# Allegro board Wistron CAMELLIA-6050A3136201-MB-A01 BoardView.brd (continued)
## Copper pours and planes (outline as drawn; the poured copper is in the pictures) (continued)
VRP1V8A on BOTTOM: 117.49,92.31 116.89,91.72 117.05,91.56 114.7,89.22 114.43,89.22 111.89,91.76 111.78,91.76 111.25,92.29 111.25,93.89 114.2,96.84 115.47,96.84 118.64,93.66 118.64,93.16 117.68,92.19 117.64,92.17
VRP1V8A_PH on BOTTOM: 108.23,100.78 108.73,100.27 109.37,100.27 110,100.9 110.64,100.9 111.91,99.63 111.91,99.13 108.92,96.14 107.34,97.73 107.34,99.25 107.85,99.76 107.85,100.4
VRP1V8A_VIN on BOTTOM (solid shape): 105.58,102.53 105.58,102.12 106.27,101.44 106.58,101.44 107.29,100.73 107.29,100.67 106.7,100.09 104.87,100.09 104.62,100.34 104.19,100.34 104.02,100.18 103.74,100.18 102.1,101.82 102.1,102.99 101.11,103.98 101.11,105.22 101.88,105.98 102.13,105.98
VRP2V5 on BOTTOM: 201.42,7.43 201.42,3.24 202.94,3.24 202.94,4.26 203.07,4.38 205.23,4.38 205.36,4.51 205.36,7.3 205.23,7.43
VRP2V5_PH on BOTTOM: 200.53,7.3 200.53,3.37 200.4,3.24 197.1,3.24 196.97,3.37 196.97,4.64 197.1,4.76 198.5,4.76 198.62,4.89 198.62,7.3 198.75,7.43 200.4,7.43
VRP2V5_VIN on BOTTOM: 195.45,4.13 195.32,4 194.18,4 194.05,4.13 194.05,4.26 193.8,4.51 192.78,4.51 192.66,4.38 192.66,3.24 192.53,3.11 191.87,3.11 191.87,5.65 192.27,5.65 192.78,5.15 193.93,5.15 194.18,4.89 195.32,4.89 195.45,4.76
VRP3V3A on BOTTOM: 223.54,64.58 226.59,64.58 226.84,64.84 227.86,64.84 228.88,65.85 228.88,70.68 229.13,70.93 229.13,73.09 229,73.22 223.67,73.22 223.42,72.96 223.42,64.71
VRP3V3A_PH on BOTTOM (solid shape): 228.04,79.95 228.5,79.95 228.62,79.82 228.62,79.44 229.46,78.6 227.73,78.6 227.73,80.56 228.04,80.56
VRP3V3A_PH on BOTTOM: 227.73,78.81 228.62,78.81 228.62,78.68 230.53,78.68 230.78,78.42 230.78,76.27 230.53,76.01 225.19,76.01 224.94,76.27 224.94,78.04 225.32,78.42 227.48,78.42 227.73,78.68
VRP3V3A_VIN on BOTTOM: 225.57,81.85 225.96,81.47 226.84,81.47 226.97,81.35 226.97,80.46 227.23,80.2 227.48,80.2 227.48,80.58 227.86,80.96 227.86,87.11 227.78,87.19 226.08,87.19 225.57,86.68
VRP5V0 on BOTTOM: 240.43,63.06 240.94,63.57 241.83,63.57 241.96,63.69 241.96,65.72 240.69,66.99 237.39,66.99 237.26,66.87 237.26,66.36 236.24,65.34 235.73,65.34 235.1,65.98 233.45,65.98 233.32,65.85 233.32,65.34 232.31,64.33 232.31,63.06 233.19,63.06 233.45,63.31 233.45,63.57 233.58,63.69 235.23,63.69 235.86,63.06
VRP5V0_PH on BOTTOM (solid shape): 237.92,72.76 238.45,72.23 238.45,72.2 236.85,72.2 237.49,72.84 237.49,76.44 237.92,76.44
VRP5V0_PH on BOTTOM: 237.51,72.61 237.51,72.96 236.75,72.2 235.86,72.2 235.73,72.07 235.73,70.55 235.86,70.42 241.45,70.42 242.47,71.44 242.47,71.57 242.34,71.69 240.81,71.69 240.56,71.95 240.56,72.58 238.02,72.58 237.99,72.61
VRP5V0_VIN on BOTTOM: 235.35,76.65 235.1,76.39 233.7,76.39 233.58,76.27 233.58,73.6 233.7,73.47 236.62,73.47 237.26,74.11 237.26,76.65 237.77,77.15 237.77,79.95 237.64,80.08 237,80.08 236.12,79.19 235.86,79.19 235.86,78.04 235.35,77.54
VRP5V0A on BOTTOM: 186.2,91.12 193.06,91.12 193.7,90.49 193.7,86.68 184.68,86.68 184.55,86.81 184.55,88.33 186.08,89.85 186.08,91
VRP5V0A_PH on BOTTOM (solid shape): 189.96,97.14 189.96,96.36 190.4,95.92 190.4,93.92 190.27,93.79 185.82,93.79 185.7,93.92 185.7,95.52 186.1,95.92 186.1,96.64 186.15,96.69 187.33,96.69 187.48,96.84 189.05,96.84 189.43,97.22 189.89,97.22
VRP5V0A_VIN on BOTTOM (solid shape): 184.68,100.78 188.03,100.78 188.03,100.14 188.19,99.98 188.64,99.98 188.73,99.89 188.73,99.61 188.87,99.22 189.22,98.99 189.25,98.99 189.25,97.75 189.23,97.73 188.36,97.73 188.03,98.06 185.49,98.06 184.55,99 183.16,99 183.03,99.13 183.03,100.65 183.31,100.93 183.41,100.99 183.41,101.03 183.66,101.28 184.17,101.28
VRPCHG_HG1 on BOTTOM: 176.68,109.54 175.41,109.54 175.28,109.41 175.28,108.02 175.41,107.89 176.68,107.89 176.81,108.02 176.81,109.41
VRPCHG_HG2 on BOTTOM: 156.74,109.67 155.98,109.67 155.85,109.54 155.85,108.52 155.6,108.27 155.6,107.76 155.85,107.51 156.23,107.51 156.49,107.76 156.49,108.02 156.87,108.4 156.87,109.54
VRPCHG_LG1 on BOTTOM: 178.08,111.06 176.68,111.06 176.55,110.94 176.55,110.05 177.06,109.54 177.44,109.54 178.2,110.3 178.2,110.94
VRPCHG_LG2 on BOTTOM: 157.88,116.91 157.88,115.38 158.01,115.25 158.77,115.25 158.9,115.38 158.9,117.03 158.65,117.29 158.26,117.29
VRPCHG_PH1 on BOTTOM: 169.06,107.89 174.9,107.89 175.03,108.02 175.03,109.54 175.28,109.79 175.79,109.79 176.3,110.3 176.3,115.25 176.17,115.38 174.39,115.38 174.14,115.13 173.12,115.13 173,115.25 173,116.14 172.87,116.27 172.11,116.27 171.22,115.38 167.28,115.38 167.28,109.67
VRPCHG_PH2 on BOTTOM (solid shape): 163.22,110.81 162.33,109.92 155.9,109.92 155.9,113.43 155.22,114.11 155.22,114.75 155.47,115 163.22,115
VRPCPU_PH1 on BOTTOM: 143.12,103.62 145.59,103.62 145.64,103.57 145.64,100.27 145.89,100.01 148.94,100.01 148.94,97.22 141.75,97.22 141.63,97.35 141.63,100.27 141.75,100.4 142.9,100.4 143.02,100.52 143.02,103.52
VRPCPU_PH2 on BOTTOM: 116.81,101.17 118.56,102.92 118.62,102.92 120.96,100.59 121.32,100.59 122.23,101.5 124.23,99.51 124.23,99.38 120.8,95.95 120.55,95.95 118.01,98.49 118.01,99.8 116.81,100.99
VRPCPU_PH3 on BOTTOM: 127.48,100.83 129.22,102.57 129.29,102.57 131.63,100.24 131.98,100.24 134.14,102.39 134.9,101.64 134.9,97.47 134.77,97.35 130.77,97.35 127.48,100.65
VRPGT_PH1 on BOTTOM: 109.98,60.31 110.11,60.44 110.11,63.95 109.9,64.15 105.97,64.15 105.69,64.43 105.69,67.25 105.56,67.38 103.2,67.38 103.12,67.3 103.12,64.45 103.78,63.79 103.78,60.52 103.98,60.31
VRPRIM_VIN on BOTTOM (solid shape): 178.18,101.44 178.18,97.6 177.9,97.32 177.9,97.12 177.52,97.12 177.44,97.19 177.44,97.98 176.02,99.4 176.02,101.64 176.17,101.79 177.82,101.79
VRPSA_PH1 on BOTTOM: 151.41,102.05 153.18,102.05 153.18,100.27 153.06,100.14 153.06,98.62 153.31,98.36 154.84,98.36 155.09,98.62 156.36,98.62 156.49,98.49 156.49,95.7 151.66,95.7 151.28,96.08 151.28,101.92
VRPVCC_PRIM on BOTTOM: 173.38,88.33 173.38,87.95 173.5,87.82 173.89,87.82 174.52,87.19 180.87,87.19 181.25,87.57 181.25,90.36 180.49,91.12 176.04,91.12 175.66,91.51 175.66,92.52 175.54,92.65 174.01,92.65 173.89,92.52 173.89,88.84
VRPVCC_PRIM_PH on BOTTOM: 176.17,94.55 177.14,94.55 178.05,95.47 180.57,95.47 180.74,95.29 180.74,94.81 180.87,94.68 182.01,94.68 182.14,94.55 182.14,92.9 182.01,92.78 176.55,92.78 176.17,93.16
VRPVCCIO on BOTTOM: 112.44,55.46 112.44,50.74 112.7,50.48 115.85,50.48 115.97,50.61 115.97,51.12 115.59,51.5 115.59,52.26 116,52.67 116.13,52.67 116.23,52.77 116.23,53.15 116.86,53.79 118.13,53.79 118.26,53.91 118.26,54.65 118.16,54.75 116,54.75 115.77,54.98 115.77,55.26 115.57,55.46
VRPVCCIO_PH on BOTTOM: 105.56,54.12 105.46,54.22 104.44,54.22 104.44,54.57 105.81,54.57 106.68,55.44 107.72,55.44 107.85,55.56 107.85,56.71 107.97,56.83 109.24,56.83 109.39,56.68 109.39,51.5 106.32,51.5 106.32,51.88 105.56,52.64
VRPVCCIO_VIN on BOTTOM (solid shape): 103.4,54.07 104.19,54.07 104.19,53.66 103.02,53.66 102.71,53.35 102.71,52.98 101.87,52.14 98.88,52.14 98.4,52.62 98.4,53.08 98.5,53.18 98.54,53.2 98.8,53.2 98.93,53.33 98.93,54.17 103.3,54.17
VRPVDDQ on BOTTOM: 171.14,5.6 174.34,5.6 174.34,3.24 169.87,3.24 169.59,2.96 169.59,2.48 168.96,1.84 167.92,1.84 167.66,2.1 167.66,6.42 168.04,6.8 168.04,8.7 168.93,8.7 168.93,7.3 169.95,6.29 170.46,6.29
VRPVDDQ_PH on BOTTOM: 158.9,6.92 158.9,6.16 159.03,6.03 160.17,6.03 160.55,5.65 160.55,5.15 161.19,4.51 161.19,2.61 161.57,2.22 163.98,2.22 164.11,2.35 164.11,7.43 160.3,7.43 159.92,7.05 159.03,7.05
VRPVDDQ_VIN on BOTTOM (solid shape): 155.47,6.03 155.85,6.03 155.98,6.16 157.5,6.16 158.01,5.65 158.01,5.53 157.76,5.27 156.49,5.27 156.11,4.89 156.11,4.64 155.09,3.62 151.79,3.62 151.53,3.88 151.53,5.78 151.91,6.16 155.34,6.16
VRPVTT on TOP (solid shape): 160.04,10.35 160.04,9.34 160.68,8.7 160.68,7.94 160.42,7.69 159.92,7.69 159.66,7.94 159.66,8.57 159.41,8.83 158.39,8.83 158.14,8.57 158.14,8.32 158.01,8.19 157.76,8.19 157.63,8.32 157.63,8.83 158.14,9.34 158.14,10.86 158.52,11.24 159.15,11.24

Small or netless copper shapes (teardrops, artwork), in the pictures only: 2352 on TOP, 3084 on BOTTOM, 1684 on L3, 30 on L4, 822 on L5, 1427 on L6

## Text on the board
Ref Des/Silkscreen Bottom: 6050A3140501 | -ALS-A01(A1) | 6050A3136301-USB-A01(A1) | 6050A3194001-ALS-A01(A1) | HSN-I36C | HSN-I36C-4 | UMA
Ref Des/Silkscreen Top: CN9354 | MIC9352 | MIC9350 | CAMELLIA-6050A3136201-MB-A01(A1) | HSN-I36C | HSN-I36C-4 | UMA | 6050A3140701-MIC-A01(A1)
User.15: TP24_NP | 100pF_50V_1 | TOSHIBA_SSM3K15AMFV_3P | short_0201_10 | 1uF_6.3V_1 | 0.1uF_6.3V_1 | NXP_74LVC1G3157GM_TSOT886_6P | 2.2K_5%_1 | short_0402_15 | 10pF_50V_1 | 0.1uF_10V_1 | AMC_AZ5125_01H_SOD523_2P | FIX_MASK_0.8 | AMAZING_AZ1143_04F_R7G_10P | MCF08062G900_T | 4.7K_5%_1 | 1000pF_25V_1 | 68pF_50V_1 | 0_5%_1_NSP | 1uF_6.3V_2_NP | TI_SN74AUP1G97DCKR_SC70_6P_NP | TOSHIBA_SSM3K15AMFV_3P_NP | 0.022uF_6.3V_1 | 49.9_1%_1 | 6.8PF_50V_1 | 0.22uF_6.3V_2 | 100K_5%_1 | 0.022uF_16V_2 | short_0201_5 | 2200pF_16V_1 | 470K_1%_1 | NXP_74LVC1G17GM_TSOT886_6P | 0.22uF_6.3V_1 | NXP_PMBT3906YS_TSOT363_6P | NXP_NX5P3290AU_WLCSP_16P | 0.22uF_25V_1 | 0.33uF_25V_1 | short_0402_15_nsp | 1K_5%_1_NP | 10K_5%_1_NP | 100K_5%_1_NP | DIALOG_SLG4T43296VTR_STQFN_12P | 80.6_1%_1 | 200K_5%_1 | 6.04K_1%_1/16W_2 | 0.01UF_25V_1 | 220K_5%_1 | 2.2UF_6.3V_1 | 100K_1%_1 | NXP_74LVC1G08GW_TSOT353_5P | AMAZING_AZ5B75_01B_R7G_2P | 18pF_50V_1 | AMAZING_AZ5B8S_01F_R7G_2P | 220K_1%_1 | LITEON_LTW_C195DSKS_5A_4P | TP24 | 10uF_6.3V_2 | 4.7UF_6.3V_2 | 2.2UF_6.3V_2 | 33_5%_1 | 0.1uF_16V_2 | MST_MH255ESP_PSOT23_3P | Short_0805_50_NSP | 4.99K_1%_2 | KNOWLES_SPK0838HT4H_1_8P | CAPELLA_CM32181E_OPLGA_6P | 43.2K_1%_2 | 470pF_50V_2 | 150pF_50V_2 | short_0402_5 | 8.06K_1%_2 | 2.43K_1%_2 | 1.43K_1%_2 | 0.1uF_25V_2 | DIODE-BAT54-TAP-PHP_NP | LITTELFUSE_0805L110ULYR | 100_1%_1 | 1uF_6.3V_2 | POWERPAD1x1m | 121_1%_1 | EXCELLIANCE_MOS_EMB32N03K | 10K_5%_1 | 2.74K_1%_2 | 10pF_50V_2 | 4.7_5%_1 | 200_1%_1 | 1000PF_50V_2 | 20K_5%_1 | DIODE-BAT54-TAP-PHP | 499_1%_1 | 3.3K_5%_1 | INFINEON_SLB9670VQ2_0_FW_7_85_VQFN_32P | 1K_5%_1 | 47_5%_1 | 0.01uF_50V_2 | 49.9K_1%_2 | 300_5%_1 | LES_LBSS84LT1G_SOT23_3P | 390pF_50V_2 | 76.8K_1%_2 | 14.3K_1%_2 | 2.2_1%_1 | short_0805_40_nsp | 100pF_50V_2 | TEXAS_TPS2546RTER_QFN_16P | 17.8K_1%_2 | 33.2K_1%_2 | PARADE_PS8713BTQFN24GTR2_A3_TQFN_24P | 4.7K_5%_2 | 73.2K_1%_2 | 39pF_50V_2 | 330pF_50V_2 | 1.5K_5%_2 | 0.01uF_25V_2 | 15_5%_1 | 113_1%_1 | 1M_5%_1 | INTERSIL_ISL9241HRTZ_TQFN_32P | 82pF_50V_2 | 22_5%_1 | 51K_1%_1 | 150K_1% | CSC0201 | 43_5%_1 | 51.1K_1%_2 | 47K_5%_1 | short_0603_25 | 200K_5%_2 | short_0805_50 | 10uF_6.3V_3 | 10K_5%_2 | 100K_5%_2 | 2.2K_5%_2 | 0_5%_1 | TP30_NP | 120K_1%_2 | RSC_0402 | MPS_MP2979AGQKT_0180_Z_TQFN_48P | 150_5%_2 | 240_1%_2 | 24.9_1%_2 | 22uF_6.3V_3 | 2.2UF_6.3V_3 | L2N7002SWT1G | 2.2_5%_2 | 0.22uF_25V_3 | 100_5%_2 | 330_1%_2 | 22K_5%_2 | 470K_1%_2 | 3.3K_5%_2 | 47K_5%_2 | 806K_1%_2 | WINBOND_W25Q80DVZPIG_WSON_8P | 5.1K_1%_2 | 34K_1%_2 | 470K_5%_2 | 20K_5%_2 | 51K_1%_2 | 357K_1%_2 | 220K_5%_2 | 1UF_25V_2 | 20K_1%_2 | 300K_5%_2 | 100K_1%_2 | 150_1%_2 | BAT54C_30V_0_6A | 620K_1%_2 | 45.3_1%_2 | 49.9_1%_2 | 1.5K_1%_2 | 4.7_5%_2 | 133K_1%_2 | 150K_5%_2 | 75K_1%_2 | 470_5%_2 | 4.7uF_6.3V_3 | 301K_1%_2 | 560_5%_2 | REA_ALC3292_CG_MQFN_48P | PJX138K | 1K_5%_2 | 30_5%_2 | 0_5%_2 | ACES_50696_0060M_002_6P | CSC0402 | 51_5%_2 | RSC_0603 | 1M_5%_2 | WINBOND_W25Q128JVPIQ_WSON_8P | PANJIT_PDZ5.1B | 1K_1%_2 | SM3335PSQGC_TRG | 127K_1% | STANDOFF_3.2_6.0 | 10uF_25V_3 | 10_5%_2 | 75_5%_2 | 2M_5%_2 | 2_1%_2 | PARADE_PS8339AQFN56GTR2_A1_QFN_56P | 2.2_5%_3 | 47UF_4V_3 | SYNNEX_SM3303PSQG | CYNTEC_CMMB041B_R68MS | SCREW260_460_1P | SCREW330_600_500_1P | CSC0603 | CYPRESS_CYPD5225_96BZXIT_BGA_96P | SCREW250_600_500_1P | SINGATRON_2SJ3166_026111F_6P | ACES_50696_0120M_002_12P | 4.7_5%_3 | 10_1%_3 | SCREW250_500_1P | 0_5%_3 | NUVOTON_NPCX797HA1BX_VFBGA_144P | ACES_50951_0084N_001_8P | SCREW500_700_NP_1P | 1N4148WS | PM513BA | SCREW250_700_1P | SCREW370_700_1P | TP30 | SCREW400_700_1P | SCREW450_700_1P | SANDISK_SDINBDA4_32G_V_TFBGA_153P | SCREW250_600_1P | INTEL_TITAN_RIDGE_DP_BGA_337P | SCREW300X420_860_1P | SUYIN_020090HB024M51UZL_24P | SS3040HE | SAMTEC_BSH_030_01_L_D_A_TR_60P | FULLINHOPE_A0635_0001_7P
User.16: TP24_NP | FIX_MASK_0.8 | 0.1uF_6.3V_1 | 0.1uF_10V_1 | short_0402_15 | 0.01UF_25V_1 | short_0201_10 | DIODES_DMP2035UVT_7_TSOT26_6P | 68pF_50V_1 | 10pF_50V_1 | 100pF_50V_1 | short_0201_5 | AMC_AZ5125_01H_SOD523_2P | 2.2K_5%_1 | TOSHIBA_SSM3K15AMFV_3P | 47pF_50V_1 | 0.1uF_25V_1 | 110k_5%_1 | 100K_5%_1 | 115K_1%_1 | 220pF_50V_1 | 18pF_50V_1 | GEMALTO_WSTM056_WLCSP_11P | 4.7pF_50V_1 | 1uF_6.3V_1 | 57.6K_1%_1 | 3.3K_5%_1 | TI_SN74AUP1G97DCKR_SC70_6P | 0.22uF_6.3V_1 | NXP_74LVC1G07GW_TSSOP_5P | 18.7K_1%_1 | NXP_74LVC1G3157GM_TSOT886_6P | 1000pF_25V_1 | 2.2UF_6.3V_1 | 4.75K_0.5%_1 | 470PF_50V_1 | 0.22uF_25V_1 | 0.33uF_25V_1 | SEMTECH_RCLAMP2451ZATFT_2P | PANJIT_BAW56DW_SOT363_6P | 200K_5%_1 | 0.047uF_6.3V_1 | NXP_74LVC1G08GW_TSOT353_5P | 4.7K_5%_1 | 49.9_1%_1 | 220K_5%_1 | 60.4_1%_1 | DLM0QSN900HY2D | 200K_1%_1 | 15pF_25V_1 | 12pF_50V_1 | RICHTEK_RT8097ALGE_TSOT23_6P | 41.2K_1%_1 | 76.8K_1%_1 | 31.6K_1%_1 | 3.3K_1%_1 | 49.9K_1%_1 | MCF08062G900_T | SILERGY_SY8088A1AAC_SOT23_5P | OSRAM_NL27WZ07DFT2G_SC88_6P | 3.01K_1%_1 | TXC_7M25000153_CRYSTAL_25M_20PF_4P | AMAZING_AZ5B8S_01F_R7G_2P | 220K_1%_1 | 0.1uF_16V_2 | 33_5%_1 | 10K_5%_1 | TP24 | 2.2UF_6.3V_2 | DIODE-BAT54-TAP-PHP | NUVO_NCT3521U_SOT23_5P | 20K_5%_1 | 22_1%_1 | GMT_G524B1T11U_SOT23_5P | DIPTRONICS_T3C2QR_2P_NSP | 0.1uF_25V_2 | POWERPAD1x1m | SILERGY_SY8386RHC_QFN_16P | 49.9K_1%_2 | 220pF_50V_2 | 4.7UF_6.3V_2 | 1uF_6.3V_2 | 1K_5%_1 | 1K_1%_1 | MPS_MP86901_AGQT_TQFN_13P | 10.2K_1%_2 | ALPHA_AO6424L_TSOP_6P | NUVO_NCT7717U_SOT23_5P | LES_LBSS84LT1G_SOT23_3P | 1000PF_50V_2 | 100pF_50V_2 | 1M_5%_1 | 9.09K_1%_2 | 3300pF_50V_2 | 15.4K_1%_2 | 330pF_50V_2 | short_0402_5 | 100_1%_1 | 10M_5%_1 | 200_1%_1 | 47_5%_1 | RFL11T2SA2AR | LITTELFUSE_0805L110ULYR | 470_5%_1 | 71.5K_1%_2 | 22_5%_1 | GMT_G708T1U_SOT23_5P | GMT_G788P81U_MSOP_8P | SILERGY_SYV128CRAC_QFN_20P | 22pF_50V_2 | 10_5%_1 | 76.8K_1%_2 | YEL_LMBT3906LT1G_SOT23_3P | 3900pF_16V_2 | GMT_G2898KD1U_TDFN_15P | 32.4K_1%_2 | ON_LMV393DMR2G_SOP_8P | 1.87K_1%_2 | 27K_1%_1 | 68pF_50V_2 | 27K_5%_1 | SILERGY_SYV127CTMC_QFN_13P | 15_5%_1 | 390pF_50V_2 | MISAKI_NDTP016_G1A_AAET_4P | 200_5%_2 | 0_5%_1 | 10uF_6.3V_3 | L2N7002SWT1G | 100K_5%_2 | 4.7uF_6.3V_3 | 10K_5%_2 | short_0805_50 | 150_1%_2 | 22uF_6.3V_3 | RSC_0402 | 2.2_5%_2 | 102K_1%_2 | 4.7_5%_2 | POWERPAD_2_0805 | POWERPAD_2_0610 | 10K_1%_2 | CSC0402 | 133K_1%_2 | MPS_NB692GD_QFN_13P | 27,5% | 4.7uF_10V_3 | POWERPAD_4_0610 | 20K_5%_2 | 100_5%_2 | TAI_TECH_HPC4018B_2R2M | BAT54C_30V_0_6A | ENTERY_3703K_Q02N_11L_2P | 330K_5%_2 | 470K_5%_2 | 220K_1%_2 | 110K_1%_2 | MPS_NB680AGD_Z_QFN_12P | 4.7uF_25V_3 | AMC_AZ4024_02S_3P | 220K_5%_2 | short_0603_25 | 33K_1%_2 | 1.5K_5%_2 | 499_1%_2 | 100_1%_2 | 220_1%_2 | 49.9_1%_2 | 2.2uF_25V_3 | MPS_NB685AGQ_Z_QFN_16P | 60.4_1%_2 | 100K_1%_2 | 324K_1%_2 | 549K_1%_2 | 74LVC1G17GW | 3.32K_1% | 33pF_50V | WINBOND_W25Q256JVEIN_WSON_8P | 120OHM_25%_3A | 4.7K_5%_2 | PJX138K | 0_5%_2 | MPS_MP86948GQVT_Z_TQFN_21P | 10UF_25V_5 | 10uF_25V_3 | 1uF_25V_3 | ACES_51536_00801_Q01_8P | RSC_0603 | 1K_5%_2 | ENTERY_6718K_Y08N_01L_8P | 2.2_5%_3 | 1M_5%_2 | 3.3_5%_3 | 2K_5%_2 | 51_5%_2 | 56_5%_2 | 4.7uF_25V_5 | 100_5%_3 | LMBT3904LT1G | POWERPAD2x2M | 22UF_6.3V_5 | TXC_24MHZ_12PF | 1M_1%_2 | 22_5%_2 | ACES_50224_00401_001_4P | SCREW260_460_1P | EMI_STOP_SUL_15A8M_1P | CSC0603 | CYN_PCMC063T_R68MN_4P | MAGIC_SRPG0603_R15M_AD_D98E | SCREW330_600_500_1P | AOS_AONR36368 | LN2312LT1G | JOINT_F0504WRA_S_18PNLNK1G00L_18P | SCREW250_600_500_1P | EMC_EMB07N03V | CYN_PCMB063T_R33MS_4P | PJS6416_6P | ACES_50224_00601_001_6P | SCREW250_500_1P | ACES_50506_01001_001_10P | 0_5%_3 | 0.005_1%_6 | 330uF_2V_9mR_Pana_-35% | 1N4148WS | 10_5%_5 | ACES_50224_00701_001_7P | STANDOFF_3.2_6.0 | 100uF_6.3V | SCREW500_700_NP_1P | CSC0805 | ACES_51614_01501_002_15P | SCREW250_700_1P | SCREW370_700_1P | 0_5%_5 | SCREW400_700_1P | ENTERY_3802K_Q04N_07L_4P | SCREW450_700_1P | PM513BA | 0.01_1%_6 | 32.768KHZ_12.5PF | BAT54A | HIROSE_FH52_15S_0_5SH_15P | ACES_50950_0084N_001_8P | 4.7_5%_6 | SCREW250_600_1P | PCMC063T-1R5MN | SCREW300X420_860_1P | HIROSE_FH34SRJ_30S_0_5SH_50_30P | 33uF_16V | 15uF_25V | SINGATRON_2UB1757_000111F_9P | PCMC063T_2R2MN | ACES_50406_02001_Q01_20P | BAV99 | 1.1A_24V | ACES_50279_0090T_Q01_9P | 10k_5% | P_TWO_196652_42041_3_42P | ARGOSY_D4AR0_26010_1P40_260P | 68uF_16V | PCMB103T_1R0MS | AON6380 | LOTES_APCI0018_P005H_75P | LOTES_APCI0020_P003H_75P | I_PEX_20455_030E_14_30P | ACES_51398_0407T_001_40P | LOTES_APCI0019_P003H_75P | INTEL_J92043_BGA_1528P | T_CONN_16_A3940_1A03_A_19P
User.29: D | C | B | A | 1 | 2 | 3 | 4
User.45: FIGURE | SIZE | 10.0 | 16.0 | 22.0 | 31.0 | 98.0 | 102.0 | 126.0 | 130.0 | 146.0 | 157.0 | 177.0 | 26.38 | 33.0 | 35.0 | 37.0 | 40.0 | 41.0 | 42.0 | 43.0 | 47.0 | 51.0 | 59.0 | 63.0 | 71.0 | 79.0 | 158.0 | 197.0 | 47.0x24.0 | 49.0x28.0 | 51.0x24.0 | 55.0x20.0 | 63.0x35.0 | 71.0x22.0 | 71.0x24.0 | 73.0x28.0 | 75.0x24.0 | 75.0x28.0 | 165.0x118.0 | 32.0x26.0 | 38.0x34.0 | 47.0x43.0 | 55.0x37.0 | 63.0x51.0 | 67.0x63.0 | 99.0x79.0 | DRILL CHART: TOP to BOTTOM | ALL UNITS ARE IN MILS | PLATED | NON-PLATED | QTY | 176 | 57 | 4750 | 550 | 1 | 19 | 18 | 7 | 3 | 4 | 2 | 5 | 8
